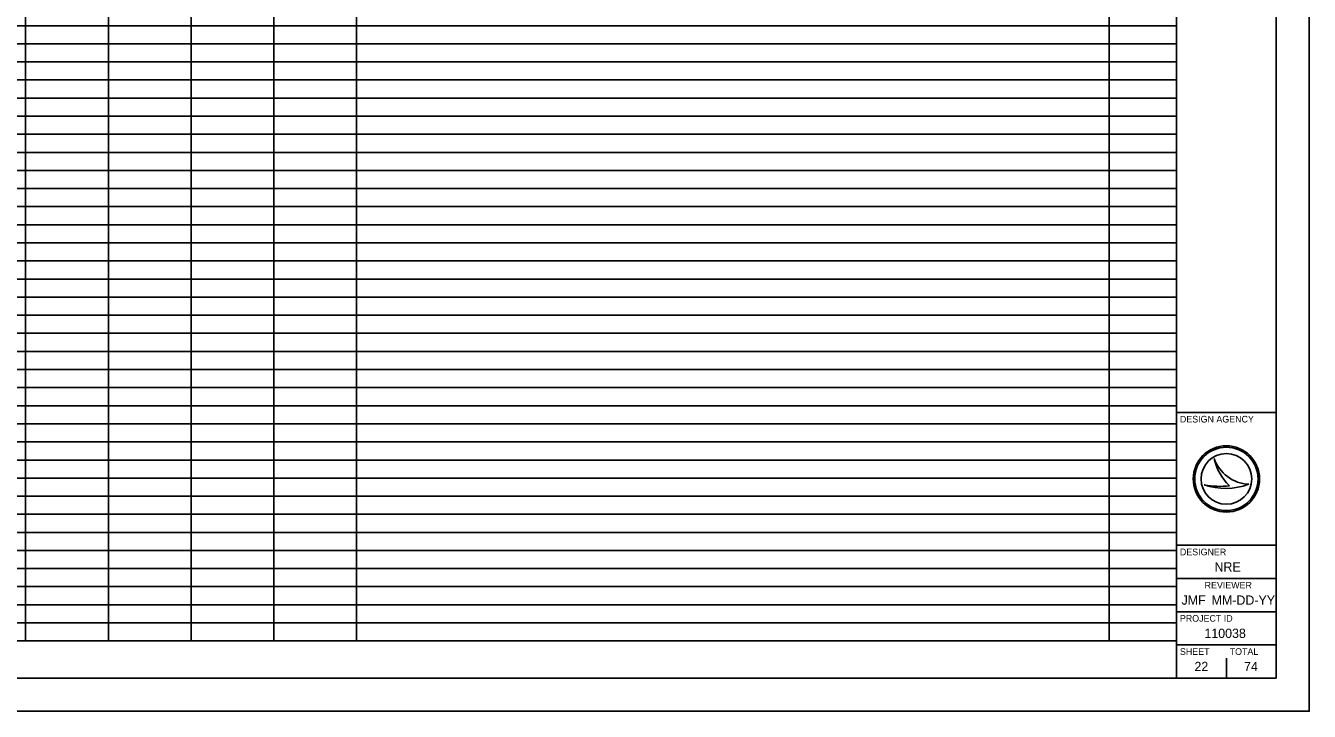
# Model space of a CAD drawing. Extents: x 0 to 34, y 0 to 22.
# Drawn here: x 14.66 to 34, y 0 to 10.33 of the extents above; entities that cross this region are included whole.
import ezdxf

# ---------------------------------------------------------------- set-up
doc = ezdxf.new("R2010")
doc.units = 0
for name, color, linetype in [('Default', 7, 'Continuous'), ('SH_Border', 7, 'Continuous'), ('SH_Cut_Line', 7, 'Continuous'), ('SH_Data', 7, 'Continuous')]:
    doc.layers.add(name, color=color, linetype=linetype)

msp = doc.modelspace()

# ---------------------------------------------------------------- linework, layer by layer
at = {"layer": 'Default'}
for p, q in [((14.659, 10.599), (14.659, 10.326)), ((15.905, 10.599), (15.905, 10.326)), ((17.151, 10.599), (17.151, 10.326)), ((18.397, 10.599), (18.397, 10.326)), ((19.643, 10.599), (19.643, 10.326)), ((30.985, 10.599), (30.985, 10.326)), ((31.998, 10.599), (31.998, 10.326)), ((13.647, 10.326), (14.659, 10.326)), ((14.659, 10.326), (15.905, 10.326)), ((14.659, 10.326), (14.659, 10.054)), ((15.905, 10.326), (17.151, 10.326)), ((15.905, 10.326), (15.905, 10.054)), ((17.151, 10.326), (19.643, 10.326)), ((17.151, 10.326), (17.151, 10.054)), ((18.397, 10.326), (18.397, 10.054)), ((19.643, 10.326), (30.985, 10.326)), ((19.643, 10.326), (19.643, 10.054)), ((30.985, 10.326), (31.998, 10.326)), ((30.985, 10.326), (30.985, 10.054)), ((31.998, 10.326), (31.998, 10.054)), ((13.647, 10.054), (14.659, 10.054)), ((14.659, 10.054), (15.905, 10.054)), ((14.659, 10.054), (14.659, 9.236)), ((15.905, 10.054), (17.151, 10.054)), ((15.905, 10.054), (15.905, 9.236)), ((17.151, 10.054), (19.643, 10.054)), ((17.151, 10.054), (17.151, 9.236)), ((18.397, 10.054), (18.397, 9.236)), ((19.643, 10.054), (30.985, 10.054)), ((19.643, 10.054), (19.643, 9.236)), ((30.985, 10.054), (31.998, 10.054)), ((30.985, 10.054), (30.985, 9.236)), ((31.998, 10.054), (31.998, 9.236)), ((13.647, 9.781), (14.659, 9.781)), ((14.659, 9.781), (15.905, 9.781)), ((15.905, 9.781), (17.151, 9.781)), ((17.151, 9.781), (19.643, 9.781)), ((19.643, 9.781), (30.985, 9.781)), ((30.985, 9.781), (31.998, 9.781)), ((13.647, 9.509), (14.659, 9.509)), ((14.659, 9.509), (15.905, 9.509)), ((15.905, 9.509), (17.151, 9.509)), ((17.151, 9.509), (19.643, 9.509)), ((19.643, 9.509), (30.985, 9.509)), ((30.985, 9.509), (31.998, 9.509)), ((13.647, 9.236), (14.659, 9.236)), ((14.659, 9.236), (15.905, 9.236)), ((14.659, 9.236), (14.659, 8.691)), ((15.905, 9.236), (17.151, 9.236)), ((15.905, 9.236), (15.905, 8.691)), ((17.151, 9.236), (19.643, 9.236)), ((17.151, 9.236), (17.151, 8.691)), ((18.397, 9.236), (18.397, 8.691)), ((19.643, 9.236), (30.985, 9.236)), ((19.643, 9.236), (19.643, 8.691)), ((30.985, 9.236), (31.998, 9.236)), ((30.985, 9.236), (30.985, 8.691)), ((31.998, 9.236), (31.998, 8.691)), ((13.647, 8.964), (14.659, 8.964)), ((14.659, 8.964), (15.905, 8.964)), ((15.905, 8.964), (17.151, 8.964)), ((17.151, 8.964), (19.643, 8.964)), ((19.643, 8.964), (30.985, 8.964)), ((30.985, 8.964), (31.998, 8.964)), ((13.647, 8.691), (14.659, 8.691)), ((14.659, 8.691), (15.905, 8.691)), ((14.659, 8.691), (14.659, 7.873)), ((15.905, 8.691), (17.151, 8.691)), ((15.905, 8.691), (15.905, 7.873)), ((17.151, 8.691), (19.643, 8.691)), ((17.151, 8.691), (17.151, 7.873)), ((18.397, 8.691), (18.397, 7.873)), ((19.643, 8.691), (30.985, 8.691)), ((19.643, 8.691), (19.643, 7.873)), ((30.985, 8.691), (31.998, 8.691)), ((30.985, 8.691), (30.985, 7.873)), ((31.998, 8.691), (31.998, 7.873)), ((13.647, 8.418), (14.659, 8.418)), ((14.659, 8.418), (15.905, 8.418)), ((15.905, 8.418), (17.151, 8.418)), ((17.151, 8.418), (19.643, 8.418)), ((19.643, 8.418), (30.985, 8.418)), ((30.985, 8.418), (31.998, 8.418)), ((13.647, 8.146), (14.659, 8.146)), ((14.659, 8.146), (15.905, 8.146)), ((15.905, 8.146), (17.151, 8.146)), ((17.151, 8.146), (19.643, 8.146)), ((19.643, 8.146), (30.985, 8.146)), ((30.985, 8.146), (31.998, 8.146)), ((13.647, 7.873), (14.659, 7.873)), ((14.659, 7.873), (15.905, 7.873)), ((14.659, 7.873), (14.659, 7.328)), ((15.905, 7.873), (17.151, 7.873)), ((15.905, 7.873), (15.905, 7.328)), ((17.151, 7.873), (19.643, 7.873)), ((17.151, 7.873), (17.151, 7.328)), ((18.397, 7.873), (18.397, 7.328)), ((19.643, 7.873), (30.985, 7.873)), ((19.643, 7.873), (19.643, 7.328)), ((30.985, 7.873), (31.998, 7.873)), ((30.985, 7.873), (30.985, 7.328)), ((31.998, 7.873), (31.998, 7.328)), ((13.647, 7.601), (14.659, 7.601)), ((14.659, 7.601), (15.905, 7.601)), ((15.905, 7.601), (17.151, 7.601)), ((17.151, 7.601), (19.643, 7.601)), ((19.643, 7.601), (30.985, 7.601)), ((30.985, 7.601), (31.998, 7.601)), ((13.647, 7.328), (14.659, 7.328)), ((14.659, 7.328), (15.905, 7.328)), ((14.659, 7.328), (14.659, 6.511)), ((15.905, 7.328), (17.151, 7.328)), ((15.905, 7.328), (15.905, 6.511)), ((17.151, 7.328), (19.643, 7.328)), ((17.151, 7.328), (17.151, 6.511)), ((18.397, 7.328), (18.397, 6.511)), ((19.643, 7.328), (30.985, 7.328)), ((19.643, 7.328), (19.643, 6.511)), ((30.985, 7.328), (31.998, 7.328)), ((30.985, 7.328), (30.985, 6.511)), ((31.998, 7.328), (31.998, 6.511)), ((13.647, 7.056), (14.659, 7.056)), ((14.659, 7.056), (15.905, 7.056)), ((15.905, 7.056), (17.151, 7.056)), ((17.151, 7.056), (19.643, 7.056)), ((19.643, 7.056), (30.985, 7.056)), ((30.985, 7.056), (31.998, 7.056)), ((13.647, 6.783), (14.659, 6.783)), ((14.659, 6.783), (15.905, 6.783)), ((15.905, 6.783), (17.151, 6.783)), ((17.151, 6.783), (19.643, 6.783)), ((19.643, 6.783), (30.985, 6.783)), ((30.985, 6.783), (31.998, 6.783)), ((13.647, 6.511), (14.659, 6.511)), ((14.659, 6.511), (15.905, 6.511)), ((14.659, 6.511), (14.659, 5.421)), ((15.905, 6.511), (17.151, 6.511)), ((15.905, 6.511), (15.905, 5.421)), ((17.151, 6.511), (19.643, 6.511)), ((17.151, 6.511), (17.151, 5.421)), ((18.397, 6.511), (18.397, 5.421)), ((19.643, 6.511), (30.985, 6.511)), ((19.643, 6.511), (19.643, 5.421)), ((30.985, 6.511), (31.998, 6.511)), ((30.985, 6.511), (30.985, 5.421)), ((31.998, 6.511), (31.998, 5.421)), ((13.647, 6.238), (14.659, 6.238)), ((14.659, 6.238), (15.905, 6.238)), ((15.905, 6.238), (17.151, 6.238)), ((17.151, 6.238), (19.643, 6.238)), ((19.643, 6.238), (30.985, 6.238)), ((30.985, 6.238), (31.998, 6.238)), ((13.647, 5.966), (14.659, 5.966)), ((14.659, 5.966), (15.905, 5.966)), ((15.905, 5.966), (17.151, 5.966)), ((17.151, 5.966), (19.643, 5.966)), ((19.643, 5.966), (30.985, 5.966)), ((30.985, 5.966), (31.998, 5.966)), ((13.647, 5.693), (14.659, 5.693)), ((14.659, 5.693), (15.905, 5.693)), ((15.905, 5.693), (17.151, 5.693)), ((17.151, 5.693), (19.643, 5.693)), ((19.643, 5.693), (30.985, 5.693)), ((30.985, 5.693), (31.998, 5.693)), ((13.647, 5.421), (14.659, 5.421)), ((14.659, 5.421), (15.905, 5.421)), ((14.659, 5.421), (14.659, 5.148)), ((15.905, 5.421), (17.151, 5.421)), ((15.905, 5.421), (15.905, 5.148)), ((17.151, 5.421), (19.643, 5.421)), ((17.151, 5.421), (17.151, 5.148)), ((18.397, 5.421), (18.397, 5.148)), ((19.643, 5.421), (30.985, 5.421)), ((19.643, 5.421), (19.643, 5.148)), ((30.985, 5.421), (31.998, 5.421)), ((30.985, 5.421), (30.985, 5.148)), ((31.998, 5.421), (31.998, 5.148)), ((13.647, 5.148), (14.659, 5.148)), ((14.659, 5.148), (15.905, 5.148)), ((14.659, 5.148), (14.659, 4.058)), ((15.905, 5.148), (17.151, 5.148)), ((15.905, 5.148), (15.905, 4.058)), ((17.151, 5.148), (19.643, 5.148)), ((17.151, 5.148), (17.151, 4.058)), ((18.397, 5.148), (18.397, 4.058)), ((19.643, 5.148), (30.985, 5.148)), ((19.643, 5.148), (19.643, 4.058)), ((30.985, 5.148), (31.998, 5.148)), ((30.985, 5.148), (30.985, 4.058)), ((31.998, 5.148), (31.998, 4.058)), ((13.647, 4.876), (14.659, 4.876)), ((14.659, 4.876), (15.905, 4.876)), ((15.905, 4.876), (17.151, 4.876)), ((17.151, 4.876), (19.643, 4.876)), ((19.643, 4.876), (30.985, 4.876)), ((30.985, 4.876), (31.998, 4.876)), ((13.647, 4.603), (14.659, 4.603)), ((14.659, 4.603), (15.905, 4.603)), ((15.905, 4.603), (17.151, 4.603)), ((17.151, 4.603), (19.643, 4.603)), ((19.643, 4.603), (30.985, 4.603)), ((30.985, 4.603), (31.998, 4.603)), ((13.647, 4.331), (14.659, 4.331)), ((14.659, 4.331), (15.905, 4.331)), ((15.905, 4.331), (17.151, 4.331)), ((17.151, 4.331), (19.643, 4.331)), ((19.643, 4.331), (30.985, 4.331)), ((30.985, 4.331), (31.998, 4.331)), ((13.647, 4.058), (14.659, 4.058)), ((14.659, 4.058), (15.905, 4.058)), ((14.659, 4.058), (14.659, 3.785)), ((15.905, 4.058), (17.151, 4.058)), ((15.905, 4.058), (15.905, 3.785)), ((17.151, 4.058), (19.643, 4.058)), ((17.151, 4.058), (17.151, 3.785)), ((18.397, 4.058), (18.397, 3.785)), ((19.643, 4.058), (30.985, 4.058)), ((19.643, 4.058), (19.643, 3.785)), ((30.985, 4.058), (31.998, 4.058)), ((30.985, 4.058), (30.985, 3.785)), ((31.998, 4.058), (31.998, 3.785)), ((13.647, 3.785), (14.659, 3.785)), ((14.659, 3.785), (15.905, 3.785)), ((14.659, 3.785), (14.659, 2.695)), ((15.905, 3.785), (17.151, 3.785)), ((15.905, 3.785), (15.905, 2.695)), ((17.151, 3.785), (19.643, 3.785)), ((17.151, 3.785), (17.151, 2.695)), ((18.397, 3.785), (18.397, 2.695)), ((19.643, 3.785), (30.985, 3.785)), ((19.643, 3.785), (19.643, 2.695)), ((30.985, 3.785), (31.998, 3.785)), ((30.985, 3.785), (30.985, 2.695)), ((31.998, 3.785), (31.998, 2.695)), ((13.647, 3.513), (14.659, 3.513)), ((14.659, 3.513), (15.905, 3.513)), ((15.905, 3.513), (17.151, 3.513)), ((17.151, 3.513), (19.643, 3.513)), ((19.643, 3.513), (30.985, 3.513)), ((30.985, 3.513), (31.998, 3.513)), ((13.647, 3.24), (14.659, 3.24)), ((14.659, 3.24), (15.905, 3.24)), ((15.905, 3.24), (17.151, 3.24)), ((17.151, 3.24), (19.643, 3.24)), ((19.643, 3.24), (30.985, 3.24)), ((30.985, 3.24), (31.998, 3.24)), ((13.647, 2.968), (14.659, 2.968)), ((14.659, 2.968), (15.905, 2.968)), ((15.905, 2.968), (17.151, 2.968)), ((17.151, 2.968), (19.643, 2.968)), ((19.643, 2.968), (30.985, 2.968)), ((30.985, 2.968), (31.998, 2.968)), ((13.647, 2.695), (14.659, 2.695)), ((14.659, 2.695), (15.905, 2.695)), ((14.659, 2.695), (14.659, 2.423)), ((15.905, 2.695), (17.151, 2.695)), ((15.905, 2.695), (15.905, 2.423)), ((17.151, 2.695), (19.643, 2.695)), ((17.151, 2.695), (17.151, 2.423)), ((18.397, 2.695), (18.397, 2.423)), ((19.643, 2.695), (30.985, 2.695)), ((19.643, 2.695), (19.643, 2.423)), ((30.985, 2.695), (31.998, 2.695)), ((30.985, 2.695), (30.985, 2.423)), ((31.998, 2.695), (31.998, 2.423)), ((13.647, 2.423), (14.659, 2.423)), ((14.659, 2.423), (15.905, 2.423)), ((14.659, 2.423), (14.659, 1.333)), ((15.905, 2.423), (17.151, 2.423)), ((15.905, 2.423), (15.905, 1.333)), ((17.151, 2.423), (19.643, 2.423)), ((17.151, 2.423), (17.151, 1.333)), ((18.397, 2.423), (18.397, 1.333)), ((19.643, 2.423), (30.985, 2.423)), ((19.643, 2.423), (19.643, 1.333)), ((30.985, 2.423), (31.998, 2.423)), ((30.985, 2.423), (30.985, 1.333)), ((31.998, 2.423), (31.998, 1.333)), ((13.647, 2.15), (14.659, 2.15)), ((14.659, 2.15), (15.905, 2.15)), ((15.905, 2.15), (17.151, 2.15)), ((17.151, 2.15), (19.643, 2.15)), ((19.643, 2.15), (30.985, 2.15)), ((30.985, 2.15), (31.998, 2.15)), ((13.647, 1.878), (14.659, 1.878)), ((14.659, 1.878), (15.905, 1.878)), ((15.905, 1.878), (17.151, 1.878)), ((17.151, 1.878), (19.643, 1.878)), ((19.643, 1.878), (30.985, 1.878)), ((30.985, 1.878), (31.998, 1.878)), ((13.647, 1.605), (14.659, 1.605)), ((14.659, 1.605), (15.905, 1.605)), ((15.905, 1.605), (17.151, 1.605)), ((17.151, 1.605), (19.643, 1.605)), ((19.643, 1.605), (30.985, 1.605)), ((30.985, 1.605), (31.998, 1.605)), ((13.647, 1.333), (14.659, 1.333)), ((14.659, 1.333), (15.905, 1.333)), ((14.659, 1.333), (14.659, 1.06)), ((15.905, 1.333), (17.151, 1.333)), ((15.905, 1.333), (15.905, 1.06)), ((17.151, 1.333), (19.643, 1.333)), ((17.151, 1.333), (17.151, 1.06)), ((18.397, 1.333), (18.397, 1.06)), ((19.643, 1.333), (30.985, 1.333)), ((19.643, 1.333), (19.643, 1.06)), ((30.985, 1.333), (31.998, 1.333)), ((30.985, 1.333), (30.985, 1.06)), ((31.998, 1.333), (31.998, 1.06)), ((13.647, 1.06), (14.659, 1.06)), ((14.659, 1.06), (15.905, 1.06)), ((15.905, 1.06), (17.151, 1.06)), ((17.151, 1.06), (19.643, 1.06)), ((19.643, 1.06), (30.985, 1.06)), ((30.985, 1.06), (31.998, 1.06))]:
    msp.add_line(p, q, dxfattribs=at)
at = {"layer": 'SH_Border'}
for p, q in [((32, 0.5), (32, 21.5)), ((32, 4.5), (33.5, 4.5)), ((32, 2.5), (33.5, 2.5)), ((32, 2), (33.5, 2)), ((32, 1.5), (33.5, 1.5)), ((32, 1), (33.5, 1))]:
    msp.add_line(p, q, dxfattribs=at)
msp.add_lwpolyline([(1.5, 21.5), (33.5, 21.5), (33.5, 0.5), (1.5, 0.5)], close=True, dxfattribs=at)
at = {"layer": 'SH_Cut_Line'}
msp.add_lwpolyline([(0, 0), (34, 0), (34, 22), (0, 22)], close=True, dxfattribs=at)
at = {"layer": 'SH_Data'}
for p, q in [((32.567, 3.81), (32.567, 3.81)), ((32.75, 3.5), (32.75, 3.5)), ((32.417, 3.41), (32.417, 3.41)), ((33.087, 3.419), (33.087, 3.419)), ((32.75, 0.5), (32.75, 0.8)), ((32.375, 0.675), (32.375, 0.675))]:
    msp.add_line(p, q, dxfattribs=at)
for radius in [0.5, 0.477, 0.477, 0.382]:
    msp.add_circle((32.75, 3.5), radius, dxfattribs=at)
for centre, radius, start, end in [((33.116, 3.998), 0.58, 198.9257, 198.9319), ((33.347, 3.97), 0.796, 191.6379, 191.6421), ((33.116, 3.998), 0.58, 198.9319, 267.1657), ((33.347, 3.97), 0.796, 191.6421, 226.0947), ((32.739, 4.37), 1.013, 251.4576, 290.0832), ((32.648, 4.654), 1.266, 259.4964, 259.4995), ((32.739, 4.37), 1.013, 251.4527, 251.4576), ((32.648, 4.654), 1.266, 259.4995, 276.6672)]:
    msp.add_arc(centre, radius, start, end, dxfattribs=at)

# ---------------------------------------------------------------- texts
for s, height, p in [('DESIGN AGENCY', 0.1, (32.05, 4.35)), ('DESIGNER', 0.1, (32.05, 2.35)), ('NRE', 0.14, (32.571, 2.105)), ('REVIEWER', 0.1, (32.422, 1.85)), ('JMF', 0.14, (32.075, 1.605)), ('MM-DD-YY', 0.14, (32.527, 1.605)), ('PROJECT ID', 0.1, (32.05, 1.35)), ('110038', 0.14, (32.419, 1.105)), ('SHEET', 0.1, (32.05, 0.85)), ('TOTAL', 0.1, (32.8, 0.85)), ('22', 0.14, (32.269, 0.605)), ('74', 0.14, (33.016, 0.605))]:
    msp.add_text(s, height=height, dxfattribs=at).set_placement(p)

doc.saveas('drawing.dxf')
